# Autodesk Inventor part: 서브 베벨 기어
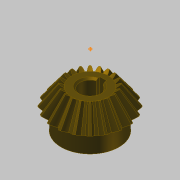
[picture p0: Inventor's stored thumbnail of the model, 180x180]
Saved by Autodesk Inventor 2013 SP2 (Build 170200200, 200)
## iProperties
Created: 2016-04
Part Number: 서브 베벨 기어
Material: 강철, 탄소
Document SubType Name: Modeling
Designer: mdu
Categories: <?xml version="1.0" encoding="UTF-16"?> <MemberInstance><Categories><FamilyTemplate><FamilyTemplateParameter ValueType="xs:double" Id="1" ObjectReferenceKey="da
Mass: 134.866 g
Surface Area: 63.6518 cm^2
Volume: 17.1585 cm^3
Density: 7.86 g/cm^3
CustomPartVersion: 1
Author: mdu
Revision Number: 1
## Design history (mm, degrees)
node "맨 위 점"
node "메쉬 평면2"
sketch "톱니 본체 스케치"
  geometry: L1 (0, 0)-(18.003, -31.331); L2 (18.003, -31.331)-(21.664, -28.891); L3 (21.664, -28.891)-(0, 0); L4 (20, -30)-(0, 0); L5 (10.813, -18.818)-(13.012, -17.352); L6 (18.003, -31.331)-(10.813, -18.818); L7 (21.664, -28.891)-(13.012, -17.352); L8 (0, -39.387)-(0, 6.564) reference; L9 (0, -30)-(21.664, -30)
  constraints: 16 end point, 4 point on line, 3 perpendicular, 2 collinear, 1 horizontal alignment, 1 vertical alignment
  dimensions: "d0" = 40 diameter of L4.start L8 (= da_de); "d1" = 36.00616 diameter of L1.end L8 (= da_dfe); "d2" = 43.3282 diameter of L2.end L8 (= da_dae); "d3" = 14.4 distance between parallel lines of L2 L5 (= da_b); "d4" = 28.8906 vertical distance of L2.end L1.start (= da_ve)
revolve "톱니 본체" sketch "톱니 본체 스케치" stored, may be unused: angle "d5" = 90 deg
node "시작점"
node "톱니 평면"
sketch "시작 스케치"
  geometry: L1 (0, -23.505)-(0, 10.645) reference; L2 (-0.834, -2.928)-(0.834, -2.928); A1 r 8.898 centre (-9.698, -3.713) between (-0.834, -2.928) and (-3.903, 3.04); A2 r 8.898 centre (9.698, -3.713) between (3.903, 3.04) and (0.834, -2.928); A3 r 27.357 centre (0, -24.037) between (3.903, 3.04) and (-3.903, 3.04); 1 further point
  constraints: 6 point on circle, 3 centre point, 3 symmetric about line, 2 end point, 1 coincident, 1 perpendicular, 1 other
  dimensions: "d7" = 8.89846 radius of A1 (= fd_rr); "d8" = 9.69794 horizontal distance of point (0, -24.037) A1.centre (= fd_x); "d9" = 20.32439 vertical distance of point (0, -24.037) A1.centre (= fd_y); "d57" = 27.35701 radius of A3 (= 0.5 x fd_dva + 0.3 x da_he); "d58" = 21.10901 distance from line of A3.centre L2 (= 0.5 x fd_dva - 1.12 x da_he)
node "끝점"
  node "끝 평면"
sketch "3D 스케치 오른쪽"
  node "Helical Curve Right" dims "d65" = 229.90621 (computed from da_dm, da_delta, da_beta), "d66" = 31.5, "d67" = 40 (= da_de), "d68" = -5.88003 (= -da_delta), "d69" = 12.16458 (computed from fd_loft, da_delta)
node "끝 평면 오른쪽"
sketch "끝 스케치 오른쪽"
  geometry: L1 (0, -22.649)-(0, 12.15) reference; L2 (-0.497, -1.72)-(0.497, -1.72); A1 r 5.299 centre (-5.775, -2.187) between (-0.497, -1.72) and (-2.324, 1.834); A2 r 5.299 centre (5.775, -2.187) between (2.324, 1.834) and (0.497, -1.72); A3 r 16.291 centre (0, -14.29) between (2.324, 1.834) and (-2.324, 1.834); 1 further point
  constraints: 6 point on circle, 3 centre point, 3 symmetric about line, 2 end point, 1 coincident, 1 perpendicular, 1 other
  dimensions: "d70" = 5.77526 horizontal distance of A3.centre A1.centre (computed from fd_x, fd_ratio); "d71" = 12.10346 vertical distance of point (0, -14.29) A1.centre (computed from fd_y, fd_ratio); "d72" = 5.29916 radius of A1 (computed from fd_rr, fd_ratio); "d73" = 12.57071 distance from line of point (0, -14.29) L2 (computed from d58, fd_ratio); "d74" = 16.29149 radius of A3 (computed from d57, fd_ratio)
feature "로프트 오른쪽" sketch "끝 스케치 오른쪽" dims "d75" = 0, "d77" = 0, "d79" = 0, "d80" = 90 deg, "d85" = 20, "d92" = 90 deg, "d93" = 90 deg, "da_teethtype" = 0 [user parameter]
sketch "3D 스케치 왼쪽"
  node "Helical Curve Left" dims "d26" = 229.90621 (computed from da_dm, da_delta, da_beta), "d27" = 12.16458 (computed from fd_loft, da_delta), "d28" = 40 (= da_de), "d29" = -5.88003 (= -da_delta)
node "끝 평면 왼쪽"
sketch "끝 스케치 왼쪽" dims "d56" = 10.82768 (derived)
  geometry: L1 (0, -35.087)-(0, 18.089) reference; L2 (-0.497, -1.716)-(0.497, -1.716); A1 r 5.299 centre (-5.775, -2.183) between (-0.497, -1.716) and (-2.324, 1.838); A2 r 5.299 centre (5.775, -2.183) between (2.324, 1.838) and (0.497, -1.716); A3 r 16.291 centre (0, -14.287) between (2.324, 1.838) and (-2.324, 1.838); 2 further points; 1 other entity
  constraints: 6 point on circle, 3 centre point, 3 symmetric about line, 2 end point, 1 coincident, 2 other
  dimensions: "d30" = 5.29916 radius of A1 (computed from fd_rr, fd_ratio); "d31" = 5.77526 horizontal distance of point (0, -14.287) A1.centre (computed from fd_x, fd_ratio); "d32" = 12.10346 vertical distance of A1.centre point (0, -14.287) (computed from fd_y, fd_ratio); "d61" = 16.29149 radius of A3 (computed from d57, fd_ratio); "d62" = 12.57071 distance from line of point (0, -14.287) L2 (computed from d58, fd_ratio)
feature "로프트 왼쪽" sketch "끝 스케치 왼쪽" dims "d35" = 0, "d37" = 0, "d39" = 0, "d40" = 90 deg, "d84" = 10, "d90" = 90 deg, "d91" = 90 deg, "da_teethtype" = 0 [user parameter]
sketch "본체 스케치"
  geometry: L1 (0, -35.038)-(0, -19.531) reference; L2 (18.003, -31.331)-(10.813, -18.818) reference; L3 (10.813, -18.818)-(0, -18.818); L4 (18.003, -31.331)-(0, -31.331)
  constraints: 4 end point, 2 perpendicular, 2 point on line
revolve "본체 고정" sketch "본체 스케치" stored, may be unused: angle "d46" = 90 deg
feature "피치 지름" dims angle "d47" = 90 deg
sketch "스케치8"
  geometry: C1 r 17 at (0, 0); 1 further point
  constraints: 1 centre point, 1 coincident
  dimensions: "d94" = 34 diameter of C1
extrude "돌출1" join sketch "스케치8" distance "d95" = 10; taper "d96" = 0 deg
sketch "스케치9"
  geometry: 1 further point
hole "구멍1" sketch "스케치9" at (0, 0) diameter "d97" = 12; stored, may be unused: countersink angle "d101" = 90 deg, drill point angle "d103" = 118 deg; dims "d98" = 6, "d99" = 4, "d100" = 2, "d102" = 8
sketch "스케치10"
  geometry: 1 further point
sketch "스케치11"
  geometry: 1 further point
sketch "스케치12"
  geometry: L1 (-2, 5.657)-(-2, 7.8); L2 (-2, 7.8)-(2, 7.8); L3 (2, 7.8)-(2, 5.657); A1 r 6 centre (0, 0) between (-2, 5.657) and (2, 5.657) reference; 1 further point
  constraints: 6 end point, 2 parallel, 2 point on circle, 1 perpendicular, 1 vertical
  dimensions: "d104" = 4 distance of L1.end L2.end; "d105" = 13.8 dimension on A1 L2
extrude "돌출2" cut sketch "스케치12" stored distance "d106" = 7; taper "d107" = 0 deg
chamfer "모따기1" distance "d108" = 1; stored, may be unused: second distance "d109" = 2, angle "d110" = 45 deg
body "Solid1"
feature "로프트" dims "d17" = 0, "d18" = 90 deg, "d19" = 0, "d20" = 90 deg, "d89" = 0, "da_teethtype" = 0 [user parameter]
pattern_circular "원형 패턴" dims angle "d22" = 360 deg, "d88" = 0, "da_teethtype" = 0 [user parameter]
pattern_circular "원형 패턴 오른쪽" dims angle "d82" = 360 deg, "da_teethtype" = 0 [user parameter]
pattern_circular "원형 패턴 왼쪽" dims angle "d42" = 360 deg, "da_teethtype" = 0 [user parameter]
sketch "끝 스케치"
  geometry: L1 (0, -15.359)-(0, 6.983) reference; L2 (-0.497, -1.72)-(0.497, -1.72); A1 r 5.299 centre (-5.775, -2.187) between (-0.497, -1.72) and (-2.324, 1.834); A2 r 5.299 centre (5.775, -2.187) between (2.324, 1.834) and (0.497, -1.72); A3 r 16.291 centre (0, -14.29) between (2.324, 1.834) and (-2.324, 1.834); 1 further point
  constraints: 6 point on circle, 3 centre point, 3 symmetric about line, 2 end point, 1 coincident, 1 other
  dimensions: "d12" = 5.29916 radius of A1 (computed from fd_rr, fd_ratio); "d15" = 5.77526 horizontal distance of A1.centre point (0, -14.29) (computed from fd_x, fd_ratio); "d16" = 12.10346 vertical distance of A1.centre point (0, -14.29) (computed from fd_y, fd_ratio); "d59" = 16.29149 radius of A3 (computed from d57, fd_ratio); "d60" = 12.57071 distance from line of A3.centre L2 (computed from d58, fd_ratio)
sketch "Sketch6"
  geometry: L1 (20, -30)-(0, 0) reference; L2 (0, -37.8)-(0, 6.3) reference
body "Srf1"
other parameters: "da_b" = 14.4 [user parameter; used in 2 equation terms], "da_de" = 40 [user parameter; used in 4 equation terms], "da_dae" = 43.3282 [user parameter; used in 2 equation terms], "da_dfe" = 36.00616 [user parameter; used in 1 equation term], "da_le" = 36.05551 [user parameter; used in 1 equation term], "da_omega" = 90 deg [user parameter; used in 1 equation term], "da_beta" = 0 [user parameter; used in 2 equation terms], "da_delta" = 5.88003 [user parameter; used in 8 equation terms], "da_alpha" = 20 deg [user parameter; used in 2 equation terms], "da_he" = 4.4 [user parameter; used in 4 equation terms], "da_ve" = 28.8906 [user parameter; used in 1 equation term], "fd_dv" = 48.07402 (computed from da_de, da_delta) [user parameter; used in 1 equation term], "fd_dva" = 52.07402 (computed from da_dae, da_delta) [user parameter; used in 3 equation terms], "fd_dvb" = 45.1748 (computed from fd_dv, da_alpha) [user parameter; used in 2 equation terms], "da_zv" = 240.37008 [user parameter; used in 1 equation term], "fd_loft" = 14.62 (= da_b + 0.05 x da_he) [user parameter; used in 4 equation terms], "fd_ratio" = 5.95514 (computed from da_le, fd_loft) [user parameter; used in 15 equation terms], "fd_rr" = 8.89846 (computed from fd_dd, fd_dvb) [user parameter; used in 6 equation terms], "fd_angle" = 0.66075 (computed from da_zv) [user parameter; used in 4 equation terms], "fd_x1" = 1.58709 (computed from da_dvw, fd_angle) [user parameter; used in 1 equation term], "fd_y1" = 23.98456 (computed from da_dvw, fd_angle) [user parameter; used in 1 equation term], "fd_x2" = 8.11084 (computed from fd_rr, fd_angle2, fd_angle) [user parameter; used in 1 equation term], "fd_y2" = 3.66016 (computed from fd_rr, fd_angle2, fd_angle) [user parameter; used in 1 equation term], "fd_x" = 9.69794 (= fd_x1 + fd_x2) [user parameter; used in 4 equation terms], "fd_y" = 20.32439 (= fd_y1 - fd_y2) [user parameter; used in 4 equation terms], "fd_angle2" = 3.57832 (computed from fd_dvb, fd_dd, da_alpha) [user parameter; used in 2 equation terms], "fd_dd" = 48.55402 (= fd_dva - 0.8 x da_he) [user parameter; used in 2 equation terms], "da_dvw" = 48.07402 [user parameter; used in 2 equation terms], "d11" = 14.62 (= fd_loft), "da_dm" = 32.01232 [user parameter; used in 2 equation terms], "da_x" = 0 [user parameter], "da_m" = 2 [user parameter], "d48" = 0, "d49" = 0, "d50" = 90 deg (= da_omega), "d51" = 9 deg (computed from da_z), "d52" = 0, "d53" = 0, "d54" = 0
